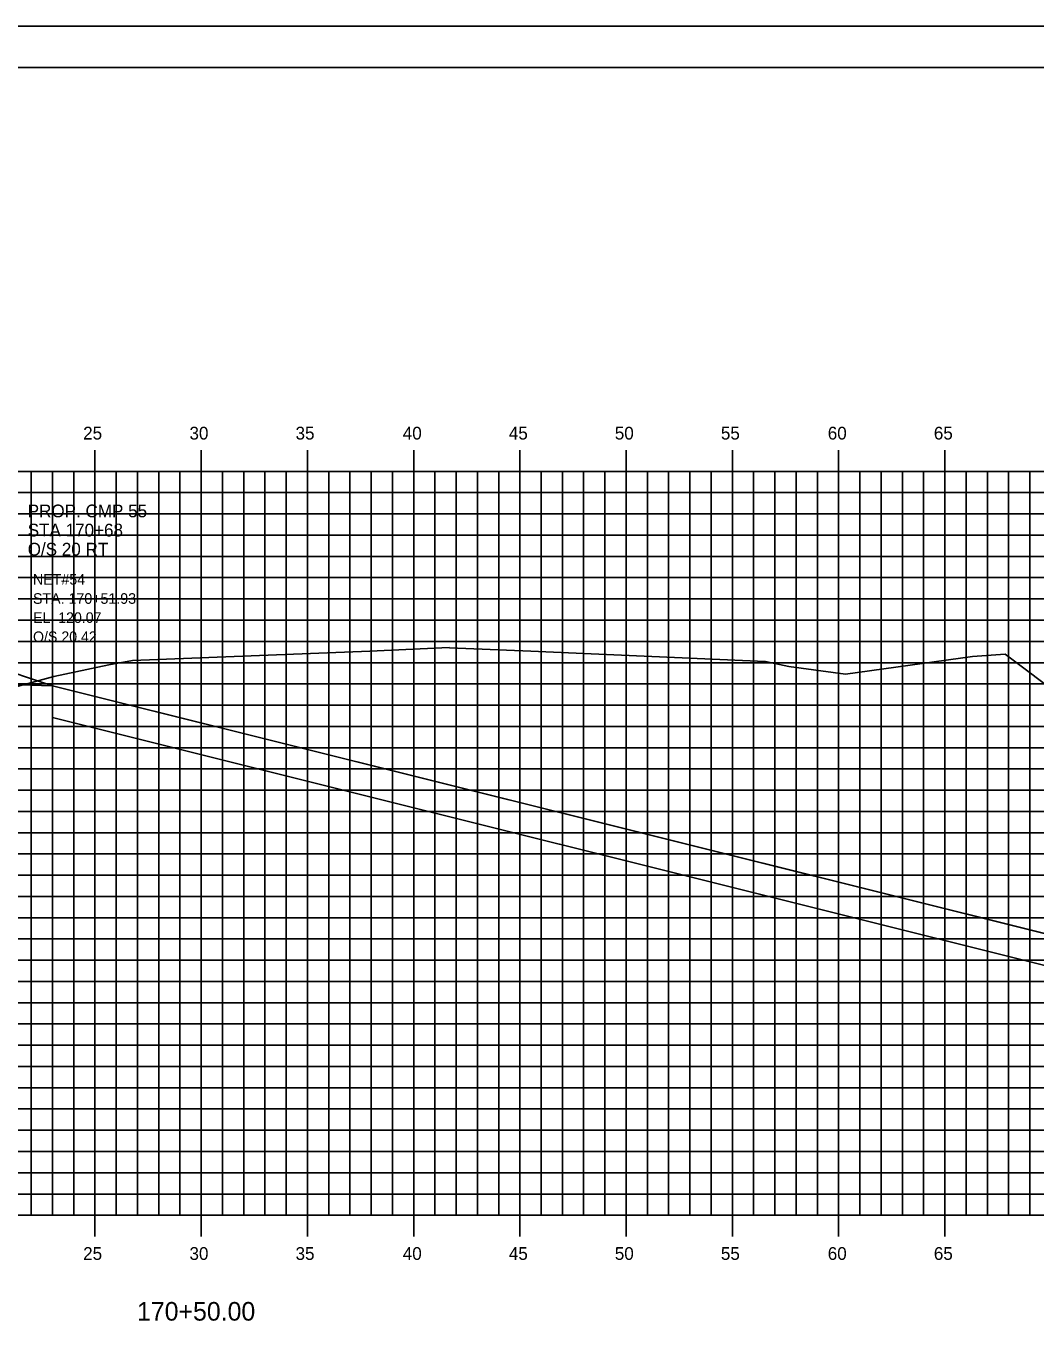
# Model space of a CAD drawing. Extents: x 850598 to 870284, y 366541 to 366651.
# Drawn here: x 855773.1 to 855820.6, y 366589.2 to 366651.2 of the extents above; entities that cross this region are included whole.
import ezdxf

# ---------------------------------------------------------------- set-up
doc = ezdxf.new("R2010")
doc.units = 0
for name, color, linetype in [('BORDER', 7, 'Continuous'), ('D_Drainage_RipRap', 7, 'Continuous'), ('D_Roadway_Centerline', 7, 'Continuous'), ('D_Roadway_SlopeLines', 7, 'Continuous'), ('D_Roadway_SubGrade', 7, 'Continuous'), ('D_Text_Monospaced', 7, 'Continuous'), ('H_V ANNOTATION', 7, 'Continuous'), ('MAJOR', 7, 'Continuous'), ('MINOR', 7, 'Continuous'), ('PLOT BOUNDARY', 7, 'Continuous'), ('S_Roadway_Centerline', 7, 'Continuous'), ('S_Utilities_Pole_Joint', 7, 'Continuous')]:
    doc.layers.add(name, color=color, linetype=linetype)

msp = doc.modelspace()

# ---------------------------------------------------------------- linework, layer by layer
at = {"layer": 'BORDER'}
msp.add_line((855866.298, 366649.225), (855706.298, 366649.225), dxfattribs=at)
at = {"layer": 'D_Drainage_RipRap'}
msp.add_lwpolyline([(855822.006, 366608.225), (855836.17, 366604.688), (855846.032, 366602.225), (855843.032, 366599.225), (855840.032, 366599.225), (855837.032, 366601.238), (855822.868, 366604.775), (855822.006, 366606.725), (855774.297, 366618.639), (855774.297, 366620.139)], close=True, dxfattribs=at)
at = {"layer": 'D_Roadway_Centerline'}
msp.add_lwpolyline([(855723.355, 366617.945), (855726.297, 366618.926), (855730.1, 366620.193), (855736.297, 366622.259), (855740.297, 366622.499), (855751.297, 366622.829), (855762.297, 366622.499), (855766.297, 366622.259), (855768.297, 366622.139), (855774.297, 366620.139), (855822.006, 366608.225), (855836.17, 366604.688), (855846.032, 366602.225), (855850.032, 366602.225)], dxfattribs=at)
at = {"layer": 'D_Roadway_SlopeLines'}
msp.add_lwpolyline([(855774.297, 366620.139), (855846.032, 366602.225), (855846.032, 366602.225)], dxfattribs=at)
at = {"layer": 'D_Roadway_SubGrade'}
msp.add_lwpolyline([(855762.297, 366621.999), (855763.297, 366621.939), (855763.297, 366622.189), (855768.297, 366621.889), (855768.297, 366622.139), (855774.297, 366620.139), (855762.297, 366620.499)], close=True, dxfattribs=at)
at = {"layer": 'MAJOR'}
for p, q in [((855776.297, 366631.227), (855776.297, 366630.225)), ((855776.297, 366631.227), (855776.297, 366630.225)), ((855781.297, 366631.227), (855781.297, 366630.225)), ((855781.297, 366631.227), (855781.297, 366630.225)), ((855786.297, 366631.227), (855786.297, 366630.225)), ((855786.297, 366631.227), (855786.297, 366630.225)), ((855791.297, 366631.227), (855791.297, 366630.225)), ((855791.297, 366631.227), (855791.297, 366630.225)), ((855796.297, 366631.227), (855796.297, 366630.225)), ((855796.297, 366631.227), (855796.297, 366630.225)), ((855801.297, 366631.227), (855801.297, 366630.225)), ((855801.297, 366631.227), (855801.297, 366630.225)), ((855806.297, 366631.227), (855806.297, 366630.225)), ((855806.297, 366631.227), (855806.297, 366630.225)), ((855811.297, 366631.227), (855811.297, 366630.225)), ((855811.297, 366631.227), (855811.297, 366630.225)), ((855816.297, 366631.227), (855816.297, 366630.225)), ((855816.297, 366631.227), (855816.297, 366630.225)), ((855711.297, 366630.225), (855851.297, 366630.225)), ((855711.297, 366630.225), (855851.297, 366630.225)), ((855711.297, 366630.225), (855851.297, 366630.225)), ((855711.297, 366630.225), (855851.297, 366630.225)), ((855776.297, 366595.225), (855776.297, 366630.225)), ((855776.297, 366595.225), (855776.297, 366630.225)), ((855781.297, 366595.225), (855781.297, 366630.225)), ((855781.297, 366595.225), (855781.297, 366630.225)), ((855786.297, 366595.225), (855786.297, 366630.225)), ((855786.297, 366595.225), (855786.297, 366630.225)), ((855791.297, 366595.225), (855791.297, 366630.225)), ((855791.297, 366595.225), (855791.297, 366630.225)), ((855796.297, 366595.225), (855796.297, 366630.225)), ((855796.297, 366595.225), (855796.297, 366630.225)), ((855801.297, 366595.225), (855801.297, 366630.225)), ((855801.297, 366595.225), (855801.297, 366630.225)), ((855806.297, 366595.225), (855806.297, 366630.225)), ((855806.297, 366595.225), (855806.297, 366630.225)), ((855811.297, 366595.225), (855811.297, 366630.225)), ((855811.297, 366595.225), (855811.297, 366630.225)), ((855816.297, 366595.225), (855816.297, 366630.225)), ((855816.297, 366595.225), (855816.297, 366630.225)), ((855711.297, 366625.225), (855851.297, 366625.225)), ((855711.297, 366625.225), (855851.297, 366625.225)), ((855711.297, 366620.225), (855851.297, 366620.225)), ((855711.297, 366620.225), (855851.297, 366620.225)), ((855711.297, 366615.225), (855851.297, 366615.225)), ((855711.297, 366615.225), (855851.297, 366615.225)), ((855711.297, 366610.225), (855851.297, 366610.225)), ((855711.297, 366610.225), (855851.297, 366610.225)), ((855711.297, 366605.225), (855851.297, 366605.225)), ((855711.297, 366605.225), (855851.297, 366605.225)), ((855711.297, 366600.225), (855851.297, 366600.225)), ((855711.297, 366600.225), (855851.297, 366600.225)), ((855711.297, 366595.225), (855851.297, 366595.225)), ((855711.297, 366595.225), (855851.297, 366595.225)), ((855711.297, 366595.225), (855851.297, 366595.225)), ((855711.297, 366595.225), (855851.297, 366595.225)), ((855776.297, 366594.223), (855776.297, 366595.225)), ((855776.297, 366594.223), (855776.297, 366595.225)), ((855781.297, 366594.223), (855781.297, 366595.225)), ((855781.297, 366594.223), (855781.297, 366595.225)), ((855786.297, 366594.223), (855786.297, 366595.225)), ((855786.297, 366594.223), (855786.297, 366595.225)), ((855791.297, 366594.223), (855791.297, 366595.225)), ((855791.297, 366594.223), (855791.297, 366595.225)), ((855796.297, 366594.223), (855796.297, 366595.225)), ((855796.297, 366594.223), (855796.297, 366595.225)), ((855801.297, 366594.223), (855801.297, 366595.225)), ((855801.297, 366594.223), (855801.297, 366595.225)), ((855806.297, 366594.223), (855806.297, 366595.225)), ((855806.297, 366594.223), (855806.297, 366595.225)), ((855811.297, 366594.223), (855811.297, 366595.225)), ((855811.297, 366594.223), (855811.297, 366595.225)), ((855816.297, 366594.223), (855816.297, 366595.225)), ((855816.297, 366594.223), (855816.297, 366595.225))]:
    msp.add_line(p, q, dxfattribs=at)
at = {"layer": 'MINOR'}
for p, q in [((855773.297, 366595.225), (855773.297, 366630.225)), ((855773.297, 366595.225), (855773.297, 366630.225)), ((855774.297, 366595.225), (855774.297, 366630.225)), ((855774.297, 366595.225), (855774.297, 366630.225)), ((855775.297, 366595.225), (855775.297, 366630.225)), ((855775.297, 366595.225), (855775.297, 366630.225)), ((855777.297, 366595.225), (855777.297, 366630.225)), ((855777.297, 366595.225), (855777.297, 366630.225)), ((855778.297, 366595.225), (855778.297, 366630.225)), ((855778.297, 366595.225), (855778.297, 366630.225)), ((855779.297, 366595.225), (855779.297, 366630.225)), ((855779.297, 366595.225), (855779.297, 366630.225)), ((855780.297, 366595.225), (855780.297, 366630.225)), ((855780.297, 366595.225), (855780.297, 366630.225)), ((855782.297, 366595.225), (855782.297, 366630.225)), ((855782.297, 366595.225), (855782.297, 366630.225)), ((855783.297, 366595.225), (855783.297, 366630.225)), ((855783.297, 366595.225), (855783.297, 366630.225)), ((855784.297, 366595.225), (855784.297, 366630.225)), ((855784.297, 366595.225), (855784.297, 366630.225)), ((855785.297, 366595.225), (855785.297, 366630.225)), ((855785.297, 366595.225), (855785.297, 366630.225)), ((855787.297, 366595.225), (855787.297, 366630.225)), ((855787.297, 366595.225), (855787.297, 366630.225)), ((855788.297, 366595.225), (855788.297, 366630.225)), ((855788.297, 366595.225), (855788.297, 366630.225)), ((855789.297, 366595.225), (855789.297, 366630.225)), ((855789.297, 366595.225), (855789.297, 366630.225)), ((855790.297, 366595.225), (855790.297, 366630.225)), ((855790.297, 366595.225), (855790.297, 366630.225)), ((855792.297, 366595.225), (855792.297, 366630.225)), ((855792.297, 366595.225), (855792.297, 366630.225)), ((855793.297, 366595.225), (855793.297, 366630.225)), ((855793.297, 366595.225), (855793.297, 366630.225)), ((855794.297, 366595.225), (855794.297, 366630.225)), ((855794.297, 366595.225), (855794.297, 366630.225)), ((855795.297, 366595.225), (855795.297, 366630.225)), ((855795.297, 366595.225), (855795.297, 366630.225)), ((855797.297, 366595.225), (855797.297, 366630.225)), ((855797.297, 366595.225), (855797.297, 366630.225)), ((855798.297, 366595.225), (855798.297, 366630.225)), ((855798.297, 366595.225), (855798.297, 366630.225)), ((855799.297, 366595.225), (855799.297, 366630.225)), ((855799.297, 366595.225), (855799.297, 366630.225)), ((855800.297, 366595.225), (855800.297, 366630.225)), ((855800.297, 366595.225), (855800.297, 366630.225)), ((855802.297, 366595.225), (855802.297, 366630.225)), ((855802.297, 366595.225), (855802.297, 366630.225)), ((855803.297, 366595.225), (855803.297, 366630.225)), ((855803.297, 366595.225), (855803.297, 366630.225)), ((855804.297, 366595.225), (855804.297, 366630.225)), ((855804.297, 366595.225), (855804.297, 366630.225)), ((855805.297, 366595.225), (855805.297, 366630.225)), ((855805.297, 366595.225), (855805.297, 366630.225)), ((855807.297, 366595.225), (855807.297, 366630.225)), ((855807.297, 366595.225), (855807.297, 366630.225)), ((855808.297, 366595.225), (855808.297, 366630.225)), ((855808.297, 366595.225), (855808.297, 366630.225)), ((855809.297, 366595.225), (855809.297, 366630.225)), ((855809.297, 366595.225), (855809.297, 366630.225)), ((855810.297, 366595.225), (855810.297, 366630.225)), ((855810.297, 366595.225), (855810.297, 366630.225)), ((855812.297, 366595.225), (855812.297, 366630.225)), ((855812.297, 366595.225), (855812.297, 366630.225)), ((855813.297, 366595.225), (855813.297, 366630.225)), ((855813.297, 366595.225), (855813.297, 366630.225)), ((855814.297, 366595.225), (855814.297, 366630.225)), ((855814.297, 366595.225), (855814.297, 366630.225)), ((855815.297, 366595.225), (855815.297, 366630.225)), ((855815.297, 366595.225), (855815.297, 366630.225)), ((855817.297, 366595.225), (855817.297, 366630.225)), ((855817.297, 366595.225), (855817.297, 366630.225)), ((855818.297, 366595.225), (855818.297, 366630.225)), ((855818.297, 366595.225), (855818.297, 366630.225)), ((855819.297, 366595.225), (855819.297, 366630.225)), ((855819.297, 366595.225), (855819.297, 366630.225)), ((855820.297, 366595.225), (855820.297, 366630.225)), ((855820.297, 366595.225), (855820.297, 366630.225)), ((855711.297, 366629.225), (855851.297, 366629.225)), ((855711.297, 366629.225), (855851.297, 366629.225)), ((855711.297, 366628.225), (855851.297, 366628.225)), ((855711.297, 366628.225), (855851.297, 366628.225)), ((855711.297, 366627.225), (855851.297, 366627.225)), ((855711.297, 366627.225), (855851.297, 366627.225)), ((855711.297, 366626.225), (855851.297, 366626.225)), ((855711.297, 366626.225), (855851.297, 366626.225)), ((855711.297, 366624.225), (855851.297, 366624.225)), ((855711.297, 366624.225), (855851.297, 366624.225)), ((855711.297, 366623.225), (855851.297, 366623.225)), ((855711.297, 366623.225), (855851.297, 366623.225)), ((855711.297, 366622.225), (855851.297, 366622.225)), ((855711.297, 366622.225), (855851.297, 366622.225)), ((855711.297, 366621.225), (855851.297, 366621.225)), ((855711.297, 366621.225), (855851.297, 366621.225)), ((855711.297, 366619.225), (855851.297, 366619.225)), ((855711.297, 366619.225), (855851.297, 366619.225)), ((855711.297, 366618.225), (855851.297, 366618.225)), ((855711.297, 366618.225), (855851.297, 366618.225)), ((855711.297, 366617.225), (855851.297, 366617.225)), ((855711.297, 366617.225), (855851.297, 366617.225)), ((855711.297, 366616.225), (855851.297, 366616.225)), ((855711.297, 366616.225), (855851.297, 366616.225)), ((855711.297, 366614.225), (855851.297, 366614.225)), ((855711.297, 366614.225), (855851.297, 366614.225)), ((855711.297, 366613.225), (855851.297, 366613.225)), ((855711.297, 366613.225), (855851.297, 366613.225)), ((855711.297, 366612.225), (855851.297, 366612.225)), ((855711.297, 366612.225), (855851.297, 366612.225)), ((855711.297, 366611.225), (855851.297, 366611.225)), ((855711.297, 366611.225), (855851.297, 366611.225)), ((855711.297, 366609.225), (855851.297, 366609.225)), ((855711.297, 366609.225), (855851.297, 366609.225)), ((855711.297, 366608.225), (855851.297, 366608.225)), ((855711.297, 366608.225), (855851.297, 366608.225)), ((855711.297, 366607.225), (855851.297, 366607.225)), ((855711.297, 366607.225), (855851.297, 366607.225)), ((855711.297, 366606.225), (855851.297, 366606.225)), ((855711.297, 366606.225), (855851.297, 366606.225)), ((855711.297, 366604.225), (855851.297, 366604.225)), ((855711.297, 366604.225), (855851.297, 366604.225)), ((855711.297, 366603.225), (855851.297, 366603.225)), ((855711.297, 366603.225), (855851.297, 366603.225)), ((855711.297, 366602.225), (855851.297, 366602.225)), ((855711.297, 366602.225), (855851.297, 366602.225)), ((855711.297, 366601.225), (855851.297, 366601.225)), ((855711.297, 366601.225), (855851.297, 366601.225)), ((855711.297, 366599.225), (855851.297, 366599.225)), ((855711.297, 366599.225), (855851.297, 366599.225)), ((855711.297, 366598.225), (855851.297, 366598.225)), ((855711.297, 366598.225), (855851.297, 366598.225)), ((855711.297, 366597.225), (855851.297, 366597.225)), ((855711.297, 366597.225), (855851.297, 366597.225)), ((855711.297, 366596.225), (855851.297, 366596.225)), ((855711.297, 366596.225), (855851.297, 366596.225))]:
    msp.add_line(p, q, dxfattribs=at)
at = {"layer": 'PLOT BOUNDARY'}
msp.add_lwpolyline([(855698.204, 366541.166), (855868.204, 366541.166), (855868.204, 366651.166), (855698.204, 366651.166)], close=True, dxfattribs=at)
at = {"layer": 'S_Roadway_Centerline'}
msp.add_lwpolyline([(855711.297, 366617.482), (855723.109, 366617.935), (855739.093, 366618.56), (855757.042, 366618.658), (855758.426, 366618.375), (855761.468, 366617.713), (855762.013, 366617.833), (855766.911, 366618.555), (855774.37, 366620.569), (855776.953, 366621.121), (855778.059, 366621.325), (855789.228, 366621.773), (855792.965, 366621.935), (855792.979, 366621.924), (855796.804, 366621.761), (855807.843, 366621.279), (855807.852, 366621.288), (855808.945, 366621.048), (855811.621, 366620.688), (855817.589, 366621.513), (855819.133, 366621.621), (855824.744, 366617.409), (855840.14, 366606.191), (855851.297, 366601.718)], dxfattribs=at)

# ---------------------------------------------------------------- texts
at = {"layer": 'D_Text_Monospaced'}
for s, height, p in [('NET#54 ', 0.5, (855773.382, 366624.894)), ('STA. 170+51.93', 0.49998, (855773.382, 366623.994)), ('EL. 120.07', 0.498, (855773.384, 366623.096)), ('O/S 20.42', 0.498, (855773.384, 366622.196))]:
    msp.add_text(s, height=height, dxfattribs=at).set_placement(p)
at = {"layer": 'H_V ANNOTATION'}
for s, height, p in [('25', 0.6, (855775.743, 366631.725)), ('30', 0.6, (855780.746, 366631.725)), ('35', 0.6, (855785.738, 366631.725)), ('40', 0.6, (855790.784, 366631.725)), ('45', 0.6, (855795.776, 366631.725)), ('50', 0.6, (855800.762, 366631.725)), ('55', 0.6, (855805.754, 366631.725)), ('60', 0.6, (855810.784, 366631.725)), ('65', 0.6, (855815.776, 366631.725)), ('25', 0.6, (855775.743, 366593.125)), ('30', 0.6, (855780.746, 366593.125)), ('35', 0.6, (855785.738, 366593.125)), ('40', 0.6, (855790.784, 366593.125)), ('45', 0.6, (855795.776, 366593.125)), ('50', 0.6, (855800.762, 366593.125)), ('55', 0.6, (855805.754, 366593.125)), ('60', 0.6, (855810.784, 366593.125)), ('65', 0.6, (855815.776, 366593.125)), ('170+50.00', 0.875, (855778.278, 366590.268))]:
    msp.add_text(s, height=height, dxfattribs=at).set_placement(p)
at = {"layer": 'S_Roadway_Centerline'}
for s, p in [('C', (855792.96, 366621.935)), ('L', (855792.965, 366621.927))]:
    msp.add_text(s, height=0.0146, dxfattribs=at).set_placement(p)
at = {"layer": 'S_Utilities_Pole_Joint'}
for s, p in [('PROP. CMP 55', (855773.134, 366628.064)), ('STA 170+68', (855773.134, 366627.164)), ('O/S 20 RT', (855773.134, 366626.264))]:
    msp.add_text(s, height=0.6, dxfattribs=at).set_placement(p)

doc.saveas('drawing.dxf')
